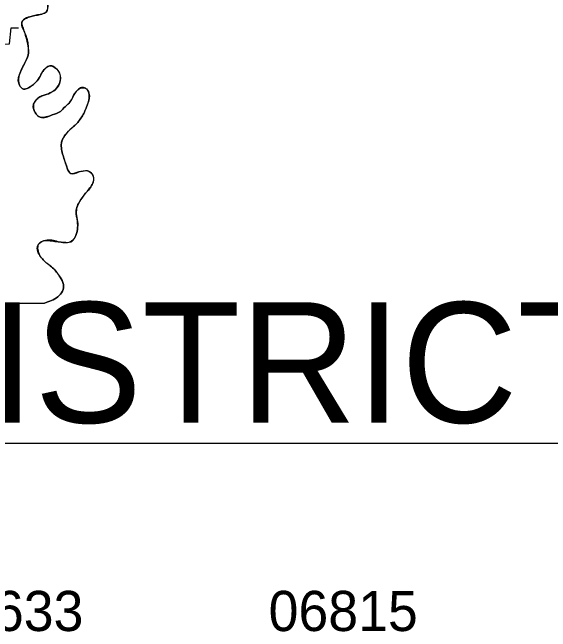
# Model space of a CAD drawing. Extents: x -12863 to 18921, y -8840 to 11152.
# Drawn here: x 14893 to 16502, y 4096 to 5947 of the extents above; entities that cross this region are included whole.
import ezdxf

# ---------------------------------------------------------------- set-up
doc = ezdxf.new("R2010")
doc.units = 0
for name, color, linetype in [('Level 1', 7, 'Continuous'), ('Level 2', 7, 'Continuous'), ('Level 48', 7, 'Continuous'), ('Level 50', 7, 'Continuous')]:
    doc.layers.add(name, color=color, linetype=linetype)

msp = doc.modelspace()

# ---------------------------------------------------------------- linework, layer by layer
at = {"layer": 'Level 1'}
msp.add_line((9301.482095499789, 4659.53902272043), (17039.07542122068, 4659.53902272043), dxfattribs=at)
for points in [[(14628.687238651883, 5913.092813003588), (14759.793752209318, 5905.2655584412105), (14765.66419307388, 5848.517963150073), (14884.051418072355, 5852.431590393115), (14888.943452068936, 5900.373524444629), (14911.446808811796, 5900.373524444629)], [(11400.923148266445, 5874.934947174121), (11402.879961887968, 5083.403831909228), (14988.740947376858, 5077.533390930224)]]:
    msp.add_lwpolyline(points, dxfattribs=at)
msp.add_spline([(15138.437190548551, 6425.777985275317), (15128.653122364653, 6403.274628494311), (15117.890647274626, 6364.138355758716), (15120.825867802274, 6330.872524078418), (15135.501969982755, 6302.4987263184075), (15158.98373366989, 6286.844217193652), (15184.422310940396, 6264.340860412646), (15182.465497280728, 6230.096621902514), (15167.789395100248, 6217.377333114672), (15133.545156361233, 6226.182994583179), (15107.128172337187, 6237.923876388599), (15084.624815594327, 6231.07502857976), (15054.294204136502, 6216.398926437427), (15031.790847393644, 6213.463705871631), (15032.769254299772, 6166.5001787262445), (15063.099865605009, 6133.2343468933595), (15089.516849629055, 6133.2343468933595), (15119.847460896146, 6129.320719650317), (15130.609936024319, 6094.098074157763), (15112.998613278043, 6064.745869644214), (15083.646408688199, 6050.069767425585), (15046.466949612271, 6067.681090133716), (15020.049965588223, 6086.270819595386), (14993.632981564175, 6103.882142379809), (14960.36714973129, 6112.687803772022), (14941.777420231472, 6108.774176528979), (14932.971758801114, 6067.681090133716), (14948.62626792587, 6030.501631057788), (14974.064845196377, 6005.06305378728), (14997.546608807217, 5971.797222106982), (14993.632981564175, 5947.33705151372), (14976.0216588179, 5940.488203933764), (14944.71264064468, 5933.639356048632), (14926.12291118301, 5923.85528790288), (14921.230876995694, 5916.028033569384), (14931.014945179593, 5882.7622016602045), (14939.8206066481, 5846.561149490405), (14939.8206066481, 5819.165758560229), (14929.058131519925, 5793.727181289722), (14912.425215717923, 5754.590908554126), (14914.382029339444, 5729.152331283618), (14926.12291118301, 5717.411449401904), (14940.799013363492, 5721.32507672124), (14960.36714973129, 5735.0227721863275), (14973.08643829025, 5750.677281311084), (14983.848913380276, 5770.245417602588), (15004.395456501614, 5786.878333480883), (15029.834033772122, 5772.202231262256), (15035.704474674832, 5741.871619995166), (15021.028372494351, 5715.454635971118), (15000.481829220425, 5703.7137541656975), (14975.043251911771, 5693.929685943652), (14956.453522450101, 5672.40473599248), (14961.345556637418, 5646.966158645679), (14976.0216588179, 5633.2684631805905), (15012.222711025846, 5640.117311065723), (15036.68288158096, 5650.879785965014), (15050.38057689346, 5664.577481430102), (15067.01349284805, 5681.210397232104), (15075.819154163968, 5697.843313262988), (15088.538442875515, 5715.454635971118), (15111.041799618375, 5720.3466699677), (15121.804274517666, 5705.670567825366), (15117.890647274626, 5672.40473599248), (15104.192952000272, 5641.095717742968), (15085.603222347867, 5614.678733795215), (15065.056679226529, 5596.089004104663), (15039.61810195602, 5555.974324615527), (15044.510135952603, 5518.794865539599), (15054.294204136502, 5488.46425427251), (15067.99189960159, 5464.982490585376), (15091.473663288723, 5469.874524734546), (15117.890647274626, 5472.809745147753), (15133.545156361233, 5460.090456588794), (15131.588342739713, 5432.695065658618), (15112.020206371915, 5406.27808163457), (15093.430476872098, 5380.839504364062), (15083.646408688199, 5345.616858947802), (15087.560035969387, 5321.156688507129), (15087.560035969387, 5298.653331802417), (15079.73278140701, 5274.193161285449), (15066.035085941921, 5260.4954658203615), (15029.834033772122, 5261.473872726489), (14991.676167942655, 5265.387499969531), (14971.129624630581, 5253.646618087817), (14975.043251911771, 5220.380786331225), (14997.546608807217, 5195.920615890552), (15013.201117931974, 5183.201327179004), (15035.704474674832, 5155.805936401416), (15045.488542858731, 5133.302579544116), (15042.553322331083, 5113.734443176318), (15028.855627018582, 5097.101527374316), (14988.740947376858, 5077.533390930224)], degree=3, dxfattribs=at)
at = {"layer": 'Level 48'}
msp.add_lwpolyline([(14631.614324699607, 5078.118045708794), (14631.623416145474, 5078.118030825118), (14988.740947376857, 5077.5333909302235)], dxfattribs=at)
for points in [[(15121.661369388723, 5706.351098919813), (15117.693944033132, 5714.240746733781), (15114.582426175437, 5717.568837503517), (15111.041799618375, 5720.3466699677), (15105.536857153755, 5722.240748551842), (15099.321507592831, 5721.742618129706), (15093.340464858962, 5719.32350512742), (15088.538442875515, 5715.454635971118), (15081.73205954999, 5706.911007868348), (15075.819154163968, 5697.843313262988), (15073.7107614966, 5693.573332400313), (15071.874186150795, 5689.150424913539), (15067.01349284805, 5681.210397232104), (15050.38057689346, 5664.577481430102), (15036.68288158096, 5650.879785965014), (15012.222711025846, 5640.117311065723), (14994.163819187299, 5634.274851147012), (14984.991667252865, 5632.814965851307), (14976.0216588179, 5633.2684631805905), (14967.80928710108, 5638.2561016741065), (14961.345556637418, 5646.966158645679), (14955.74789837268, 5659.798869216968), (14956.453522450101, 5672.40473599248), (14959.608056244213, 5678.629280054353), (14963.80594561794, 5684.50281399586), (14975.043251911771, 5693.929685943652), (14981.36111749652, 5696.863055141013), (14987.787853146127, 5699.095178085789), (14994.201932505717, 5701.190572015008), (15000.481829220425, 5703.7137541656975), (15021.028372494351, 5715.454635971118), (15035.704474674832, 5741.871619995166), (15036.976760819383, 5749.252973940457), (15036.742983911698, 5756.96600694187), (15034.522342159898, 5764.714499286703), (15029.834033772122, 5772.202231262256), (15023.714002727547, 5778.716426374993), (15017.176233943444, 5783.896120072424), (15004.395456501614, 5786.878333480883), (14993.667567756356, 5780.575528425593), (14983.848913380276, 5770.245417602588), (14980.672952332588, 5765.359003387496), (14978.205101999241, 5760.364007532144), (14975.868538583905, 5755.417682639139), (14973.08643829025, 5750.677281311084), (14960.36714973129, 5735.0227721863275), (14940.799013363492, 5721.32507672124), (14933.529451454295, 5717.917808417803), (14926.12291118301, 5717.411449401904), (14919.349953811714, 5721.765964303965), (14914.382029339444, 5729.152331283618), (14911.879046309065, 5735.526897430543), (14910.621269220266, 5742.047651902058), (14910.754668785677, 5748.480390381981), (14912.425215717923, 5754.590908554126), (14929.058131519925, 5793.727181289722), (14939.8206066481, 5819.165758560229), (14939.8206066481, 5846.561149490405), (14931.014945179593, 5882.7622016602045), (14928.591049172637, 5891.132124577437), (14925.874270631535, 5899.4526757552), (14923.281812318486, 5907.744447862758), (14921.230876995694, 5916.028033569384), (14922.479122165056, 5920.201301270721), (14924.174857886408, 5922.097204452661), (14926.12291118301, 5923.85528790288), (14944.71264064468, 5933.639356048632), (14952.500508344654, 5935.605566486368), (14960.344874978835, 5937.175384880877), (14968.200378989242, 5938.6894008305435), (14976.0216588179, 5940.488203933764), (14985.027388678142, 5942.974356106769), (14989.38414267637, 5944.757066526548), (14993.632981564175, 5947.33705151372), (14997.546608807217, 5971.797222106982), (14986.807794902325, 5988.807449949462), (14974.064845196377, 6005.06305378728), (14965.142185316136, 6013.944817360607), (14955.916155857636, 6022.383737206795)], [(14988.740947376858, 5077.533390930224), (15028.855627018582, 5097.101527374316), (15042.553322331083, 5113.734443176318), (15045.488542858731, 5133.302579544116), (15035.704474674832, 5155.805936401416), (15013.201117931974, 5183.201327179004), (14997.546608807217, 5195.920615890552), (14975.043251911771, 5220.380786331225), (14967.590680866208, 5236.750834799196), (14967.523746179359, 5245.700897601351), (14971.129624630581, 5253.646618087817), (14975.52255873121, 5258.314968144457), (14980.493512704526, 5262.082543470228), (14991.676167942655, 5265.387499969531), (15001.209652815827, 5264.771651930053), (15010.745099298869, 5263.64530738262), (15020.285546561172, 5262.411652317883), (15029.834033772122, 5261.473872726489), (15047.935007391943, 5260.019361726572), (15066.035085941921, 5260.4954658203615), (15074.060948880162, 5265.42508444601), (15077.107578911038, 5269.630626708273), (15079.73278140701, 5274.193161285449), (15087.560035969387, 5298.653331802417), (15087.560035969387, 5321.156688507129), (15086.739788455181, 5327.288437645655), (15085.454830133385, 5333.405300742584), (15084.244067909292, 5339.512900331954), (15083.646408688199, 5345.616858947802), (15084.078277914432, 5354.766925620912), (15085.777904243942, 5363.944242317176), (15093.430476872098, 5380.839504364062), (15112.020206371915, 5406.27808163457), (15131.588342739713, 5432.695065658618), (15136.409689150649, 5445.995172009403), (15133.545156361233, 5460.090456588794), (15130.53951124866, 5464.653364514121), (15126.88471183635, 5468.672050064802), (15117.890647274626, 5472.809745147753), (15104.679098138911, 5471.969563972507), (15091.473663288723, 5469.874524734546), (15085.53115961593, 5468.218983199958), (15079.601893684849, 5465.944034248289), (15073.738071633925, 5464.411322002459), (15067.99189960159, 5464.982490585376), (15065.077246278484, 5466.540064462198), (15062.696107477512, 5468.766904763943), (15059.154453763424, 5474.67707841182), (15054.294204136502, 5488.46425427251), (15044.510135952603, 5518.794865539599), (15039.984589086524, 5537.396360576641), (15039.61810195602, 5555.974324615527), (15041.060526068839, 5561.5885960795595), (15043.215044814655, 5566.994989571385), (15049.228975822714, 5577.257077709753), (15065.056679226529, 5596.089004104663), (15070.149839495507, 5600.952790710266), (15075.498774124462, 5605.359671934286), (15080.763297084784, 5609.778651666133), (15085.603222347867, 5614.678733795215), (15104.192952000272, 5641.095717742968), (15117.890647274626, 5672.40473599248), (15122.058391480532, 5688.881431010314), (15121.804274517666, 5705.670567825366), (15121.661369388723, 5706.351098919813)]]:
    msp.add_spline(points, degree=3, dxfattribs=at)

# ---------------------------------------------------------------- texts
at = {"layer": 'Level 2'}
msp.add_text('ARKANSAS HIGHWAY DISTRICTS 2, 3, & 7', height=360, dxfattribs=at).set_placement((9288.251399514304, 4720.468611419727))
at = {"layer": 'Level 50'}
for s, p in [('06633', (14659.078032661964, 4097.986173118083)), ('06633', (14659.078032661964, 4097.986173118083)), ('06815', (15659.078032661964, 4097.986173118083))]:
    msp.add_text(s, height=120, dxfattribs=at).set_placement(p)

doc.saveas('drawing.dxf')
